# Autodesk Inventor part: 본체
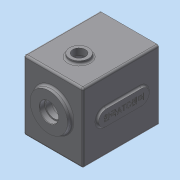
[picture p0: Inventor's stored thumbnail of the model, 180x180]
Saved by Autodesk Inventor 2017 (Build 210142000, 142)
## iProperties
Created: 2016-02
Part Number: 본체
Material: 알루미늄 6061
Document SubType Name: Modeling
Designer: mduedu
Density: 2.7 g/cm^3
Appearance: 기본값
Mass: 1511.55 g
Surface Area: 1073.15 cm^2
Volume: 559.832 cm^3
Author: mduedu
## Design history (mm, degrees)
sketch "스케치1"
  geometry: L1 (-47, -47)-(47, -47); L2 (47, -47)-(47, 63); L3 (47, 63)-(-47, 63); L4 (-47, 63)-(-47, -47); 2 further points
  constraints: 8 end point, 2 parallel, 1 horizontal, 1 midpoint, 1 perpendicular, 1 vertical alignment
  dimensions: "d0" = 94 distance of L2.end L3.end; "d155" = 110 distance of L1.end L2.end; "d156" = 47 distance from line of L1 point (0, 0)
extrude "돌출1" new body sketch "스케치1" distance "d2" = 120; taper "d3" = 0 deg
sketch "스케치3"
  geometry: L1 (47, -47)-(-47, -47) reference; L2 (47, 63)-(47, -47) reference; L3 (-47, 63)-(47, 63) reference; L4 (-47, -47)-(-47, 63) reference; L5 (37, 53)-(37, -37); L6 (37, -37)-(-37, -37); L7 (-37, -37)-(-37, 53); L8 (-37, 53)-(37, 53); 1 further point
  constraints: 8 end point, 3 other
  dimensions: "d226" = 10 distance between parallel lines of L8 L3
extrude "돌출3" cut sketch "스케치3" distance "d11" = 110; taper "d12" = 0 deg
sketch "스케치4"
  geometry: C1 r 21 at (0, 11); 1 further point
  constraints: 1 centre point, 1 vertical alignment
  dimensions: "d13" = 21 radius of C1; "d227" = 11 distance of point (0, 0) C1.centre
extrude "돌출4" join sketch "스케치4" distance "d16" = 7; taper "d17" = 0 deg
sketch "스케치5"
  geometry: C1 r 15 at (0, -20); 1 further point
  constraints: 1 centre point, 1 vertical alignment
  dimensions: "d18" = 15 radius of C1; "d20" = 20 distance of point (0, 0) C1.centre
extrude "돌출5" join sketch "스케치5" distance "d21" = 7; taper "d22" = 0 deg
sketch "스케치6"
  geometry: C1 r 30 at (0, 11); A1 r 21 centre (0, 11) between (8.978, -7.984) and (-8.978, -7.984) reference; 1 further point
  constraints: 1 centre point, 1 coincident
  dimensions: "d228" = 60 diameter of C1
extrude "돌출6" join sketch "스케치6" distance "d25" = 7; taper "d26" = -3 deg
hole "구멍1" diameter "d29" = 30; stored, may be unused: countersink angle "d33" = 90 deg, drill point angle "d35" = 0 deg; dims "d30" = 6, "d31" = 4, "d32" = 2, "d34" = 7, "d269" = 10, "d270" = 10
hole "구멍2" diameter "d38" = 22; stored, may be unused: countersink angle "d42" = 90 deg, drill point angle "d44" = 0 deg; dims "d36" = 10, "d37" = 10, "d39" = 6, "d40" = 4, "d41" = 2, "d43" = 7
hole "구멍3" diameter "d47" = 19; stored, may be unused: countersink angle "d51" = 90 deg, drill point angle "d53" = 0 deg; dims "d45" = 10, "d46" = 10, "d48" = 6, "d49" = 4, "d50" = 2, "d52" = 1
hole "구멍4" diameter "d56" = 30; stored, may be unused: countersink angle "d60" = 90 deg, drill point angle "d62" = 0 deg; dims "d57" = 6, "d58" = 4, "d59" = 2, "d61" = 8.3, "d271" = 10, "d272" = 10
hole "구멍5" diameter "d65" = 26; stored, may be unused: countersink angle "d69" = 90 deg, drill point angle "d71" = 0 deg; dims "d66" = 6, "d67" = 4, "d68" = 2, "d70" = 8, "d267" = 10, "d268" = 10
fillet "모깎기2" dims "d73" = 0.3
fillet "모깎기3" dims "d74" = 2
chamfer "모따기1" distance "d75" = 1; stored, may be unused: second distance "d76" = 2, angle "d77" = 45 deg
fillet "모깎기4" dims "d78" = 3
fillet "모깎기23" dims "d240" = 1
fillet "모깎기20" dims "d229" = 3
sketch "스케치23"
  geometry: L1 (-37, 53)-(37, 53) reference; L2 (37, 53)-(37, -37) reference; L3 (37, -37)-(-37, -37) reference; L4 (-37, -37)-(-37, 53) reference; L5 (44, -47)-(-44, -47) reference; L6 (47, 60)-(47, -44) reference; L7 (-44, 63)-(44, 63) reference; L8 (-47, -44)-(-47, 60) reference; C1 r 10 at (-37, 53); C2 r 10 at (37, 53); C3 r 10 at (-37, -37); C4 r 10 at (37, -37); A1 r 3 centre (-44, -44) between (-47, -44) and (-44, -47) reference; A2 r 3 centre (44, -44) between (44, -47) and (47, -44) reference; A3 r 3 centre (44, 60) between (47, 60) and (44, 63) reference; A4 r 3 centre (-44, 60) between (-44, 63) and (-47, 60) reference; 1 further point
  constraints: 4 centre point, 4 coincident, 3 equal radius
  dimensions: "d230" = 20 diameter of C1
extrude "돌출22" join sketch "스케치23" stored distance "d235" = 10; taper "d236" = 0 deg
fillet "모깎기21" dims "d237" = 3
node "작업 평면1"
fillet "모깎기22" dims "d239" = 1
sketch "스케치12"
  geometry: A1 r 10 centre (-37, 53) between (-34.692, 43.27) and (-27.27, 50.692) reference; A2 r 10 centre (37, 53) between (27.27, 50.692) and (34.692, 43.27) reference; A3 r 10 centre (37, -37) between (34.692, -27.27) and (27.27, -34.692) reference; A4 r 10 centre (-37, -37) between (-27.27, -34.692) and (-34.692, -27.27) reference; 5 further points
  constraints: 4 coincident
hole "구멍6" sketch "스케치12" at (-37, 53), (37, 53), (37, -37), (-37, -37) diameter "d122" = 3.242; stored, may be unused: countersink angle "d126" = 90 deg, drill point angle "d128" = 120 deg; dims "d123" = 7, "d124" = 4, "d125" = 2, "d127" = 9
sketch "스케치20"
  geometry: L1 (44, 0)-(-44, 0) reference; L2 (44, -120)-(-44, -120) reference; L3 (0, 0)-(0, -120); L4 (-44, -120)-(-44, 0) reference; L5 (44, 0)-(44, -120) reference; C1 r 10 at (0, -79)
  constraints: 2 end point, 1 centre point, 1 midpoint, 1 point on line
  dimensions: "d189" = 20 diameter of C1; "d190" = 41 distance from line of C1.centre L2
extrude "돌출19" cut sketch "스케치20" stored distance "d191" = 10; taper "d192" = 0 deg
sketch "스케치18"
  geometry: C1 r 15 at (0, -79); C2 r 10 at (0, -79) reference; 1 further point
  constraints: 1 centre point, 1 concentric
  dimensions: "d174" = 30 diameter of C1
extrude "돌출17" join sketch "스케치18" distance "d175" = 5; taper "d176" = 0 deg
fillet "모깎기16" dims "d177" = 3
sketch "스케치19"
  geometry: C1 r 15 at (24.351, 79); C2 r 10 at (24.351, 79) reference; 1 further point
  constraints: 1 centre point, 1 concentric
  dimensions: "d178" = 30 diameter of C1
extrude "돌출18" cut sketch "스케치19" distance "d181" = 5; taper "d182" = 0 deg
chamfer "모따기5" distance "d183" = 1; stored, may be unused: second distance "d184" = 2, angle "d185" = 45 deg
fillet "모깎기24" dims "d242" = 3, "d243" = 3
sketch "스케치24"
  geometry: L1 (-86, 64)-(-30, 64); L2 (-30, 64)-(-30, 40); L3 (-30, 40)-(-86, 40); L4 (-86, 40)-(-86, 64); L5 (0, 0)-(0, 104) reference; L6 (-86, 52)-(-30, 52); L7 (-58, 64)-(-58, 40); A1 r 12 centre (-86, 52) between (-86, 40) and (-86, 64); A2 r 12 centre (-30, 52) between (-30, 64) and (-30, 40); A3 r 12 centre (-30, 52) between (-30, 40) and (-30, 64); A4 r 12 centre (-86, 52) between (-86, 64) and (-86, 40); 2 further points
  constraints: 12 end point, 8 point on circle, 5 midpoint, 4 centre point, 2 parallel, 2 perpendicular, 1 horizontal, 1 horizontal alignment
  dimensions: "d244" = 58 distance between parallel lines of L7 L5; "d245" = 80 dimension on A2 A1; "d246" = 24 distance between parallel lines of L3 L1
extrude "돌출23" join sketch "스케치24" distance "d247" = 3; taper "d248" = 0 deg
fillet "모깎기25" dims "d249" = 3
sketch "스케치25"
  geometry: L1 (-30, 64)-(-86, 64) reference; L2 (-86, 40)-(-30, 40) reference; A1 r 12 centre (-86, 52) between (-86, 64) and (-86, 40) reference; A2 r 12 centre (-30, 52) between (-30, 40) and (-30, 64) reference; 3 further points
  constraints: 1 horizontal alignment, 1 midpoint, 1 vertical alignment, 1 other
feature "엠보싱3" sketch "스케치25" dims "d32" = 2, "d250" = 0.5, "d251" = 0
sketch "스케치26"
  geometry: L1 (14.367, 127)-(73.633, 127) reference; L2 (0, 0)-(88, 0) reference; L3 (88, 120)-(0, 120) reference; 5 further points
  constraints: 3 vertical alignment, 2 midpoint
  dimensions: "d252" = 35 distance from line of point (44, 35) L2; "d253" = 35 distance from line of point (44, 85) L3; "d254" = 50 distance of point (44, 35) point (44, 85) (derived)
hole "구멍8" sketch "스케치26" at (44, 85), (44, 35) diameter "d255" = 6.647; stored, may be unused: countersink angle "d259" = 90 deg, drill point angle "d261" = 118 deg; dims "d256" = 6, "d257" = 4, "d258" = 2, "d260" = 8
chamfer "모따기7" distance "d262" = 0.8; stored, may be unused: second distance "d263" = 2, angle "d264" = 30 deg
node "솔리드1"
node "투영된 루프1"
node "투영된 루프4"
node "투영된 루프5"
node "투영된 루프6"
